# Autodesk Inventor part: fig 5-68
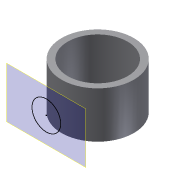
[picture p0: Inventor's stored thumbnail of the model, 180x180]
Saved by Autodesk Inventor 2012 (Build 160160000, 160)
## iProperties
Shininess: 64.0
Length Units: 11269
Angle Units: 11279
Time Units: 11290
Mass Units: 11283
Length Display Precision: 3
Angle Display Precision: 2
Compacted: True
Part Number: fig 5-68
Document SubType Name: Modeling
Created: 2002-12
Designer: deepak
Density: 1 g/cm^3
Material: Default
Density: 0.0
Volumn: 0.0
Area: 0.0
PropertySet Name: Model Information
Control State: 0
Master: False
Checked Out: False
Author: deepak
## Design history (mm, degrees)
sketch "Sketch1"
  geometry: C1 r 23.454 at (0, 0); C2 r 19.43 at (0, 0)
  constraints: 2 centre point, 1 coincident, 1 concentric
extrude "Extrusion1" new body sketch "Sketch1" stored distance "d0" = 30; taper "d1" = 0 deg
workplane "Work Plane1"
workplane "Work Plane2"
sketch "Sketch2"
  geometry: C1 r 9.343 at (0, 0)
  constraints: 1 centre point
body "Solid1"
